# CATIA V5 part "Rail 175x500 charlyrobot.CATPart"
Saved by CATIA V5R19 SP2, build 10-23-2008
Part number: Rail 175x500 charlyrobot
Bounding box of the stored display mesh (mm): x 0 to 500, y 0 to 30, z 0 to 175
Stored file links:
  Z:\fausse table rondelle-20220905T211342Z-001\fausse table rondelle\Rail 175x500 charlyrobot.CATPart
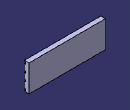
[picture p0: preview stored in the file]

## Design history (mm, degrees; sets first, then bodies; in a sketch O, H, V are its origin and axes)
AxisSystem1: origin (0, 0, 0), X (1, 0, 0), Y (0, 1, 0), Z (0, 0, 1)
Body1 (main body)
  Sketch1 on YZ plane of AxisSystem1, origin (0, 0, 0), H (0, 1, 0), V (0, 0, 1)
    line L1 (0, 0) -> (30, 0)
    line L2 (30, 0) -> (30, 175)
    line L3 (30, 175) -> (0, 175)
    line L4 (0, 175) -> (0, 0)
    distance L4 L2 = 30
    distance L3 L1 = 175
    horizontal: L1 H, L3 H
    vertical: L2 V, L4 V
  Pad1: profile Sketch1, direction (1, 0, 0), length 500
  Sketch2 on YZ plane of AxisSystem1, origin (0, 0, 0), H (0, 1, 0), V (0, 0, 1)
    point P1 (5.125, 12.5)
    line L1 (7.75, 17.75) -> (7.75, 7.25)
    line L2 (7.75, 7.25) -> (2.5, 7.25)
    line L3 (2.5, 7.25) -> (2.5, 9.25)
    line L4 (2.5, 17.75) -> (7.75, 17.75)
    point P6 (1.3125, 12.5)
    construction line L5 (5.125, 9.25) -> (5.125, 15.75)
    line L6 (2.5, 15.75) -> (-2.5, 15.75)
    line L7 (-2.5, 15.75) -> (-2.5, 9.25)
    line L8 (-2.5, 9.25) -> (2.5, 9.25)
    point P7 (5.125, 9.25)
    point P8 (5.125, 15.75)
    reference intersected line E1 through (0, 0) direction (0, 1) from ZX plane of AxisSystem1
    reference intersected line E2 through (0, 0) direction (-1, 0) from XY plane of AxisSystem1
    line L9 (2.5, 15.75) -> (2.5, 17.75)
    length L1 = 10.5
    length L4 = 5.25
    length L7 = 6.5
    distance L3 L7 = 5
    distance L3 E1 = 2.5
    distance P6 E2 = 12.5
    vertical: L1 V, L3 V, L5 V, L7 V
    horizontal: L2 H, L4 H, L6 H, L8 H
    equidistance: L1 L3 P1, L2 L4 P1, L5 L7 P6, L6 L8 P6
    midpoint: L5 P1
    coincidence: L3 L9, P7 L8, P8 L6
  Pocket1: profile Sketch2, direction (-1, 0, 0), through (limit type 3)
  Sketch3 on ZX plane of AxisSystem1, origin (0, 0, 0), H (0, 0, 1), V (1, 0, 0)
    construction line L1 (12.5, 460) -> (12.5, 500)
    point P2 (12.5, 500)
    line L2 (7.4, 460) -> (7.4, 500)
    line L3 (17.6, 500) -> (17.6, 460)
    arc A1 centre (12.5, 500) radius 5.1 from (7.4, 500) to (17.6, 500) cw
    arc A2 centre (12.5, 460) radius 5.1 from (17.6, 460) to (7.4, 460) cw
    reference intersected line E1 through (0, 0) direction (0, 1) from XY plane of AxisSystem1
    reference intersected line E2 (0, 500) -> (200, 500) from end face of Pad1
    distance L1 L2 = 5.1
    distance L1 E1 = 12.5
    length L1 = 40
    vertical: L1 V
    tangency: A1 L2, A2 L2, A1 L3, A2 L3
    coincidence: P2 E2
  Pocket2: profile Sketch3, direction (0, 1, 0), length 5
  RectPattern1: of Pocket1, Pocket2, direction 1 instances 4, spacing 50, along Z axis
